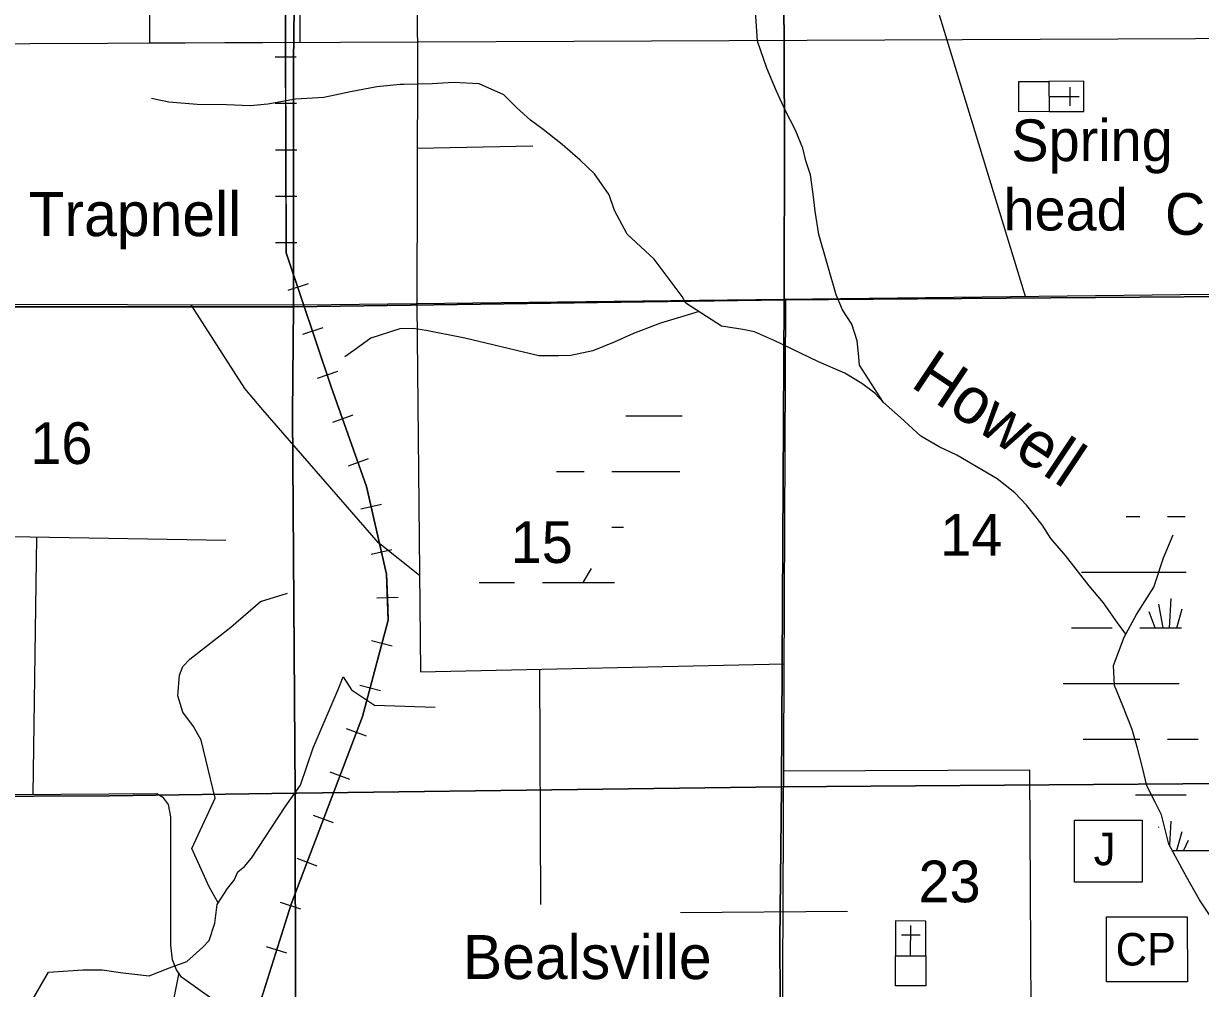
# Model space of a CAD drawing. Extents: x 380424 to 701066, y 1117407 to 1412949.
# Drawn here: x 619400 to 632096, y 1313330 to 1323738 of the extents above; entities that cross this region are included whole.
import ezdxf

# ---------------------------------------------------------------- set-up
doc = ezdxf.new("R2010")
doc.units = 0
for name, color, linetype in [('Cities Incorporated Area', 7, 'Continuous'), ('Communities and Subdivisions Names without Post Office', 7, 'Continuous'), ('Culture', 7, 'Continuous'), ('Culture Text', 7, 'Continuous'), ('Local Roads Paved', 7, 'Continuous'), ('Narrow Canals', 7, 'Continuous'), ('Narrow River Creek and Branch and Slough', 7, 'Continuous'), ('Narrow River Creek and Branch and Slough Text', 7, 'Continuous'), ('Railroads', 7, 'Continuous'), ('Section Lines', 7, 'Continuous'), ('Section Numbers', 7, 'Continuous'), ('Swamps', 7, 'Continuous')]:
    doc.layers.add(name, color=color, linetype=linetype)

msp = doc.modelspace()

# ---------------------------------------------------------------- linework, layer by layer
at = {"layer": 'Cities Incorporated Area'}
msp.add_lwpolyline([(622376, 1326397), (622382, 1323532), (620762, 1323525), (620762, 1324007)], dxfattribs=at)
at = {"layer": 'Culture'}
for p, q in [((630837, 1323115), (630462, 1323113)), ((630462, 1323113), (630463, 1322788)), ((630687, 1323052), (630688, 1322852)), ((630838, 1322790), (630837, 1323115)), ((630463, 1322951), (630788, 1322952)), ((630463, 1322788), (630838, 1322790)), ((628808, 1314058), (628808, 1313683)), ((629133, 1314057), (628808, 1314058)), ((629133, 1313682), (629133, 1314057)), ((628870, 1313908), (629071, 1313907)), ((628970, 1313682), (628971, 1314008)), ((628808, 1313683), (629133, 1313682))]:
    msp.add_line(p, q, dxfattribs=at)
for points in [[(630462, 1323113), (630463, 1322788), (630138, 1322787), (630137, 1323112)], [(630737, 1315146), (631466, 1315146), (631466, 1314475), (630737, 1314475)], [(631081, 1314101), (631954, 1314104), (631956, 1313402), (631083, 1313400)], [(628808, 1313683), (629133, 1313682), (629132, 1313357), (628807, 1313358)]]:
    msp.add_lwpolyline(points, close=True, dxfattribs=at)
at = {"layer": 'Local Roads Paved'}
for p, q in [((623648, 1322394), (624895, 1322418)), ((624967, 1316774), (624976, 1314235)), ((621075, 1313498), (620985, 1313050))]:
    msp.add_line(p, q, dxfattribs=at)
for points in [[(630208, 1320793), (629005, 1324738), (628903, 1328290)], [(628965, 1326134), (627616, 1326118), (626630, 1326102), (625277, 1326063), (623627, 1326025), (623651, 1323365), (623643, 1320709), (623682, 1316746), (627604, 1316832)], [(636855, 1323595), (636887, 1320856), (635544, 1320856), (622413, 1320702), (622413, 1320702), (609173, 1320724), (609167, 1315390)], [(638830, 1323604), (635398, 1323589), (616948, 1323509)], [(627558, 1306166), (627622, 1320763)], [(623672, 1317783), (623231, 1318136), (621980, 1319571), (621788, 1319801), (621209, 1320704)], [(616933, 1318244), (621581, 1318164)], [(619539, 1318199), (619499, 1315421)], [(630324, 1303590), (630299, 1307917), (630255, 1315684), (627599, 1315673)], [(632170, 1312857), (627569, 1312840), (622240, 1312751), (622134, 1312760), (622045, 1312795), (621948, 1312848), (621106, 1313452), (621052, 1313531), (621008, 1313638), (620990, 1313798), (620990, 1315181), (620964, 1315314), (620911, 1315385), (620840, 1315430), (618242, 1315412), (616575, 1315403), (613658, 1315385), (601152, 1315400)], [(626489, 1314149), (628289, 1314163)]]:
    msp.add_lwpolyline(points, dxfattribs=at)
at = {"layer": 'Narrow Canals'}
for points in [[(626504, 1320793), (626203, 1321198), (625913, 1321467), (625776, 1321720), (625718, 1321889), (625559, 1322116), (625406, 1322263), (625211, 1322432), (625005, 1322596), (624868, 1322696), (624720, 1322828), (624583, 1322970), (624314, 1323086), (624040, 1323102), (623807, 1323086), (623504, 1323082)], [(631292, 1317153), (631200, 1317272), (631052, 1317488), (630894, 1317673), (630640, 1318000), (630482, 1318185), (630387, 1318332), (630224, 1318538), (630092, 1318675), (629902, 1318828), (629675, 1318960), (629469, 1319082), (629279, 1319171), (629079, 1319287), (628862, 1319488), (628678, 1319652), (628583, 1319752), (628445, 1319857), (628261, 1319968), (627976, 1320089), (627490, 1320322)], [(621501, 1314255), (621403, 1314427), (621217, 1314841), (621468, 1315384), (621316, 1316008), (621234, 1316154), (621118, 1316311), (621065, 1316487), (621083, 1316708), (621118, 1316802), (621193, 1316883), (621637, 1317228), (621957, 1317502), (622249, 1317595)], [(619459, 1313140), (619669, 1313504), (620039, 1313529), (620248, 1313529), (620470, 1313498), (620754, 1313467), (620976, 1313553), (621161, 1313620), (621333, 1313774), (621401, 1313848), (621463, 1314033), (621488, 1314234), (621599, 1314407), (621673, 1314499), (621713, 1314586), (621784, 1314647), (621858, 1314734), (622221, 1315289), (622388, 1315523), (622523, 1315925), (622795, 1316554), (622850, 1316690), (622937, 1316550), (623188, 1316386), (623841, 1316363)]]:
    msp.add_lwpolyline(points, dxfattribs=at)
at = {"layer": 'Narrow River Creek and Branch and Slough'}
for points in [[(628678, 1319652), (628419, 1320053), (628408, 1320179), (628393, 1320316), (628335, 1320496), (628234, 1320649), (628165, 1320810), (627981, 1321461), (627939, 1321715), (627918, 1321899), (627891, 1322105), (627839, 1322258), (627807, 1322395), (627723, 1322596), (627622, 1322791), (627522, 1323007), (627417, 1323255), (627319, 1323547), (627295, 1323873)], [(623504, 1323082), (623464, 1323081), (623211, 1323055), (622926, 1323002), (622641, 1322939), (622335, 1322923), (622035, 1322870), (621845, 1322849), (621591, 1322860), (621275, 1322865), (620969, 1322891), (620779, 1322928)], [(627490, 1320322), (627480, 1320327), (627285, 1320411), (627158, 1320438), (626931, 1320475), (626546, 1320723), (626504, 1320793)], [(626688, 1320631), (626488, 1320570), (626272, 1320506), (625981, 1320395), (625770, 1320301), (625543, 1320206), (625306, 1320158), (625174, 1320153), (624958, 1320153), (624388, 1320290), (624161, 1320343), (623744, 1320426), (623602, 1320448), (623459, 1320445), (623148, 1320343), (622963, 1320211), (622868, 1320142)], [(632281, 1313995), (632086, 1314285), (631944, 1314533), (631754, 1314887), (631675, 1315203), (631606, 1315341), (631516, 1315515), (631474, 1315699), (631416, 1315921), (631358, 1316122), (631258, 1316380), (631168, 1316596), (631158, 1316813), (631274, 1317119), (631406, 1317362), (631595, 1317657), (631696, 1317974), (631801, 1318222)]]:
    msp.add_lwpolyline(points, dxfattribs=at)
at = {"layer": 'Railroads'}
for p, q in [((622343, 1323374), (622113, 1323374)), ((622345, 1322874), (622115, 1322874)), ((622347, 1322374), (622117, 1322374)), ((622348, 1321874), (622118, 1321874)), ((622350, 1321374), (622120, 1321374)), ((622469, 1320931), (622251, 1320858)), ((622628, 1320457), (622410, 1320384)), ((622787, 1319983), (622569, 1319910)), ((622951, 1319512), (622734, 1319436)), ((623117, 1319041), (622901, 1318964)), ((623263, 1318550), (623039, 1318498)), ((623374, 1318062), (623150, 1318011)), ((623440, 1317547), (623210, 1317539)), ((623377, 1317022), (623155, 1317081)), ((623250, 1316539), (623027, 1316598)), ((623100, 1316050), (622885, 1316132)), ((622922, 1315583), (622707, 1315664)), ((622744, 1315115), (622529, 1315197)), ((622567, 1314648), (622352, 1314730)), ((622392, 1314186), (622173, 1314256)), ((622242, 1313710), (622022, 1313779))]:
    msp.add_line(p, q, dxfattribs=at)
for points in [[(621169, 1302012), (621185, 1304666), (621217, 1306038), (621201, 1308624), (621222, 1310550), (621459, 1311615), (622288, 1314238), (623058, 1316264), (623333, 1317303), (623317, 1317799), (623100, 1318744), (622720, 1319820), (622235, 1321266), (622209, 1329571)], [(622209, 1329374), (622228, 1323374)], [(622228, 1323374), (622235, 1321266), (622720, 1319820), (623100, 1318744), (623317, 1317799), (623325, 1317543)], [(623325, 1317543), (623333, 1317303), (623058, 1316264), (622288, 1314238), (621529, 1311837)]]:
    msp.add_lwpolyline(points, dxfattribs=at)
at = {"layer": 'Section Lines'}
for points in [[(622346, 1326006), (622346, 1325979), (622312, 1323318), (622312, 1320696), (622312, 1320682), (617025, 1320681), (617025, 1320709), (617012, 1322560), (616983, 1325959), (616983, 1325979), (616996, 1325979), (622341, 1326006)], [(627611, 1326068), (627598, 1324927), (627609, 1322527), (627605, 1320789), (627605, 1320757), (622317, 1320682), (622312, 1320682), (622312, 1320696), (622312, 1323318), (622346, 1325979), (622346, 1326006)], [(632886, 1326052), (632855, 1324027), (632880, 1320796), (627605, 1320757), (627605, 1320789), (627609, 1322527), (627598, 1324927), (627611, 1326068)], [(627605, 1320757), (627576, 1315505), (622350, 1315438), (622332, 1315438), (622301, 1319527), (622312, 1320682), (622317, 1320682)], [(632880, 1320796), (632880, 1320787), (632869, 1318039), (632875, 1315546), (632865, 1315545), (627581, 1315505), (627576, 1315505), (627605, 1320757)], [(622312, 1320682), (622301, 1319527), (622332, 1315438), (620327, 1315408), (617064, 1315393), (617054, 1317559), (617025, 1320681)], [(622332, 1315438), (622332, 1315424), (622333, 1313048), (622343, 1310168), (617061, 1310125), (617061, 1310130), (617064, 1315377), (617064, 1315393), (620327, 1315408)], [(627576, 1315505), (627576, 1315497), (627560, 1313848), (627580, 1310179), (627565, 1310180), (625119, 1310199), (622343, 1310168), (622333, 1313048), (622332, 1315424), (622332, 1315438), (622350, 1315438)], [(632875, 1315546), (632875, 1315529), (632882, 1312260), (632901, 1310217), (627580, 1310179), (627560, 1313848), (627576, 1315497), (627576, 1315505), (627581, 1315505), (632865, 1315545)]]:
    msp.add_lwpolyline(points, close=True, dxfattribs=at)
at = {"layer": 'Swamps'}
for p, q in [((625898, 1319507), (626348, 1319507)), ((625148, 1318907), (625448, 1318907)), ((625748, 1318907), (626348, 1318907)), ((625525, 1317861), (625435, 1317707)), ((631693, 1317220), (631646, 1317474)), ((631764, 1317219), (631781, 1317536)), ((631608, 1317220), (631542, 1317391)), ((631840, 1314820), (631899, 1315023)), ((631917, 1314820), (631966, 1314928))]:
    msp.add_line(p, q, dxfattribs=at)
for points in [[(626348, 1319507), (626507, 1319507)], [(626348, 1318907), (626481, 1318907)], [(631293, 1318419), (631442, 1318419)], [(631742, 1318419), (631931, 1318419)], [(625748, 1318307), (625871, 1318307)], [(624317, 1317707), (624698, 1317707)], [(624998, 1317707), (625777, 1317707)], [(630813, 1317819), (631942, 1317819)], [(631840, 1317220), (631899, 1317423)], [(630705, 1317219), (631142, 1317219)], [(631442, 1317219), (631891, 1317219)], [(630614, 1316619), (631867, 1316619)], [(630831, 1316019), (631442, 1316019)], [(631742, 1316019), (632073, 1316019)], [(631396, 1315419), (631942, 1315419)], [(631648, 1315067), (631646, 1315074)], [(631767, 1314874), (631781, 1315136)], [(631801, 1314819), (632492, 1314819)]]:
    msp.add_lwpolyline(points, dxfattribs=at)

# ---------------------------------------------------------------- texts
at = {"layer": 'Communities and Subdivisions Names without Post Office'}
for s, p in [('Trapnell', (619454, 1321445)), ('Bealsville', (624140, 1313431))]:
    msp.add_text(s, height=475, rotation=0.0004, dxfattribs=at).set_placement(p)
at = {"layer": 'Culture'}
for s, rotation, p in [('J', 359.9864, (630945, 1314659)), ('CP', 0.1673, (631182, 1313577))]:
    msp.add_text(s, height=350, rotation=rotation, dxfattribs=at).set_placement(p)
at = {"layer": 'Culture Text'}
for s, p in [('Spring', (630057, 1322254)), ('Ch.', (631714, 1321459))]:
    msp.add_text(s, height=450, rotation=0.0004, dxfattribs=at).set_placement(p)
msp.add_text('head', height=450, dxfattribs=at).set_placement((629972, 1321506))
at = {"layer": 'Narrow River Creek and Branch and Slough Text'}
msp.add_text('Howell', height=500, rotation=326.3091, dxfattribs=at).set_placement((628956, 1319829))
at = {"layer": 'Section Numbers'}
for s, p in [('16', (619474, 1318987)), ('15', (624656, 1317919)), ('14', (629289, 1317997)), ('23', (629055, 1314259))]:
    msp.add_text(s, height=450, dxfattribs=at).set_placement(p)

doc.saveas('drawing.dxf')
